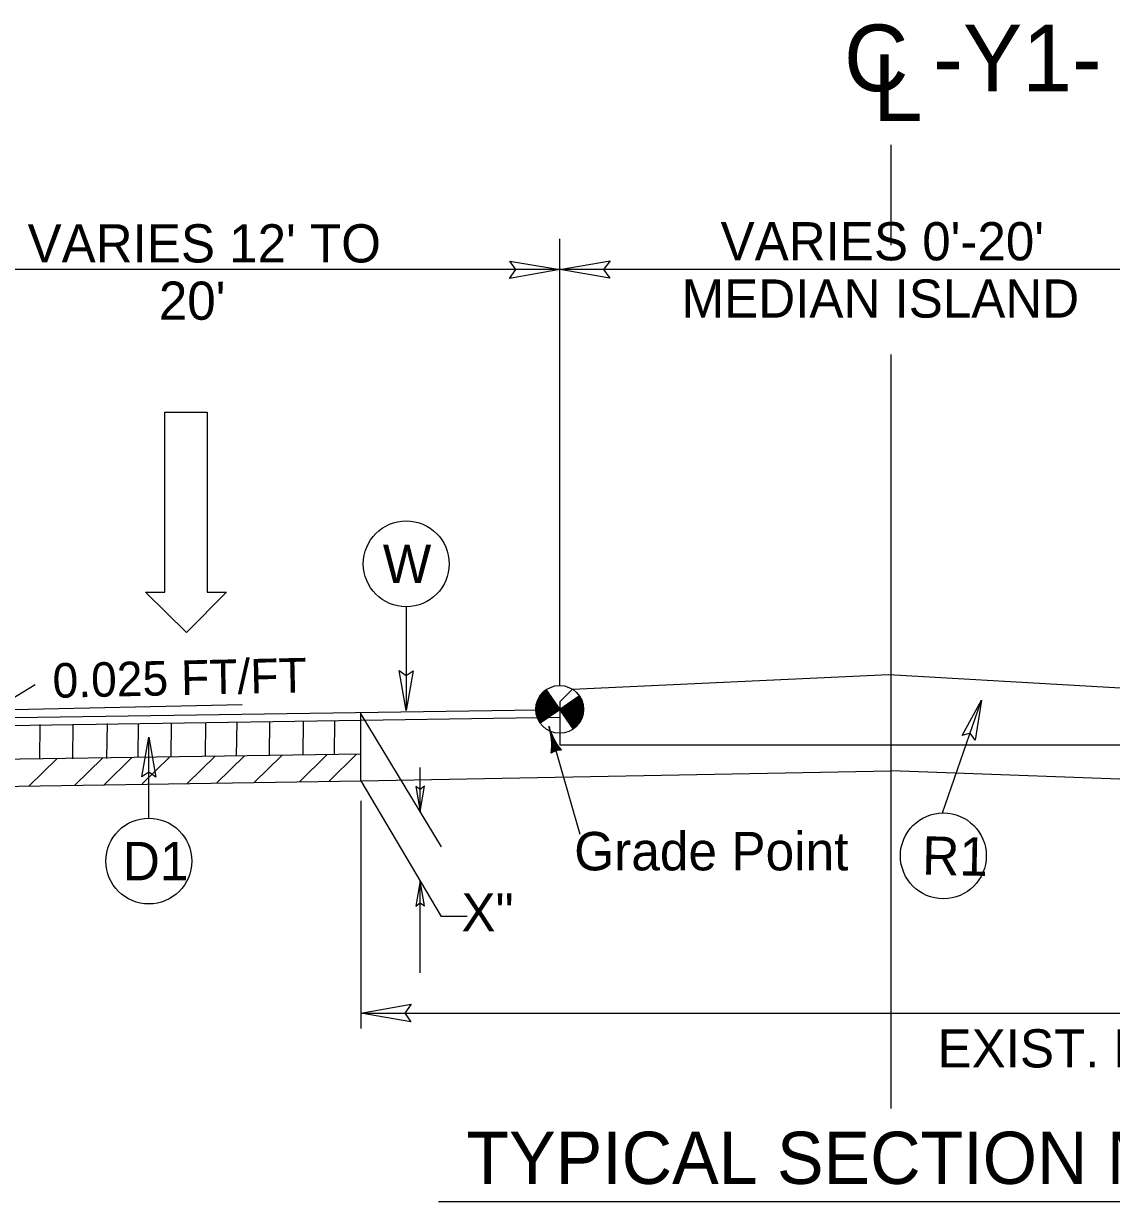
# Model space of a CAD drawing. Extents: x 2176156 to 2177167, y 76401 to 76644.
# Drawn here: x 2176967.78 to 2177000.61, y 76541.23 to 76576.8 of the extents above; entities that cross this region are included whole.
import ezdxf

# ---------------------------------------------------------------- set-up
doc = ezdxf.new("R2010")
doc.units = 0
for name, color, linetype in [('Exist Building', 7, 'Continuous'), ('Exist Building Metal Canopy', 7, 'Continuous'), ('Exist Roads Change in Surface', 7, 'Continuous'), ('Exist Roads Curbs', 7, 'Continuous'), ('Exist Roads Soil', 7, 'Continuous'), ('Exist Structure Minor Culvert Topo', 7, 'Continuous'), ('Exist Structure Minor Drop Inlet', 7, 'Continuous'), ('Exist Utilities Other Pole CELL', 7, 'Continuous'), ('Exist Vegetation Woods Line', 7, 'Continuous'), ('Model Boundary Lines Text', 7, 'Continuous'), ('Old_Level_1', 7, 'Continuous'), ('Old_Level_3', 7, 'Continuous'), ('Prop North Arrow NAD83 for Plan Sheets CELL', 7, 'Continuous'), ('Sheet Plan CELL', 7, 'Continuous')]:
    doc.layers.add(name, color=color, linetype=linetype)

msp = doc.modelspace()

# ---------------------------------------------------------------- linework, layer by layer
at = {"layer": 'Exist Building'}
for p, q in [((2176977.96, 76553.929), (2176977.96, 76556.001)), ((2176942.857, 76553.407), (2176977.96, 76553.929))]:
    msp.add_line(p, q, dxfattribs=at)
at = {"layer": 'Exist Roads Change in Surface'}
for p, q in [((2176983.548, 76556.682), (2176983.96, 76556.091)), ((2176983.96, 76556.091), (2176984.551, 76556.502)), ((2176983.367, 76555.68), (2176983.96, 76556.091)), ((2176983.96, 76556.091), (2176983.367, 76555.68)), ((2176984.371, 76555.499), (2176983.96, 76556.091))]:
    msp.add_line(p, q, dxfattribs=at)
for points in [[(2176983.714, 76556.443), (2176983.239, 76556.112)], [(2176983.698, 76556.467), (2176983.24, 76556.148)], [(2176983.706, 76556.455), (2176983.24, 76556.13)], [(2176983.69, 76556.478), (2176983.243, 76556.167)], [(2176983.682, 76556.49), (2176983.245, 76556.187)], [(2176983.673, 76556.502), (2176983.247, 76556.206)], [(2176983.665, 76556.514), (2176983.251, 76556.226)], [(2176983.657, 76556.526), (2176983.256, 76556.247)], [(2176983.649, 76556.538), (2176983.261, 76556.268)], [(2176983.64, 76556.549), (2176983.267, 76556.29)], [(2176983.632, 76556.561), (2176983.273, 76556.311)], [(2176983.624, 76556.573), (2176983.281, 76556.334)], [(2176983.616, 76556.585), (2176983.29, 76556.358)], [(2176983.607, 76556.597), (2176983.3, 76556.383)], [(2176983.599, 76556.609), (2176983.313, 76556.409)], [(2176983.591, 76556.62), (2176983.327, 76556.437)], [(2176983.583, 76556.632), (2176983.343, 76556.466)], [(2176983.574, 76556.644), (2176983.363, 76556.497)], [(2176983.566, 76556.656), (2176983.39, 76556.533)], [(2176983.558, 76556.668), (2176983.424, 76556.574)], [(2176983.55, 76556.68), (2176983.485, 76556.635)], [(2176984.555, 76556.497), (2176984.555, 76556.497), (2176983.963, 76556.085)], [(2176984.563, 76556.485), (2176983.972, 76556.073)], [(2176984.57, 76556.472), (2176983.98, 76556.062)], [(2176984.578, 76556.461), (2176983.988, 76556.05)], [(2176984.585, 76556.448), (2176983.996, 76556.038)], [(2176983.723, 76556.431), (2176983.239, 76556.094)], [(2176983.731, 76556.419), (2176983.239, 76556.077)], [(2176983.739, 76556.407), (2176983.24, 76556.06)], [(2176983.747, 76556.396), (2176983.24, 76556.042)], [(2176983.756, 76556.384), (2176983.242, 76556.026)], [(2176983.764, 76556.372), (2176983.243, 76556.01)], [(2176983.772, 76556.36), (2176983.245, 76555.993)], [(2176983.78, 76556.348), (2176983.248, 76555.978)], [(2176983.789, 76556.336), (2176983.251, 76555.962)], [(2176983.797, 76556.325), (2176983.254, 76555.947)], [(2176983.805, 76556.313), (2176983.257, 76555.931)], [(2176983.813, 76556.301), (2176983.26, 76555.916)], [(2176983.821, 76556.289), (2176983.264, 76555.901)], [(2176983.83, 76556.277), (2176983.268, 76555.887)], [(2176983.838, 76556.265), (2176983.273, 76555.872)], [(2176983.846, 76556.254), (2176983.278, 76555.858)], [(2176983.854, 76556.242), (2176983.283, 76555.844)], [(2176983.863, 76556.23), (2176983.288, 76555.83)], [(2176983.871, 76556.218), (2176983.294, 76555.816)], [(2176983.879, 76556.206), (2176983.299, 76555.803)], [(2176983.887, 76556.194), (2176983.305, 76555.789)], [(2176983.896, 76556.183), (2176983.312, 76555.776)], [(2176983.904, 76556.171), (2176983.317, 76555.763)], [(2176983.912, 76556.159), (2176983.324, 76555.75)], [(2176983.92, 76556.147), (2176983.331, 76555.737)], [(2176983.929, 76556.135), (2176983.338, 76555.724)], [(2176983.937, 76556.123), (2176983.346, 76555.713)], [(2176983.945, 76556.112), (2176983.353, 76555.7)], [(2176983.953, 76556.1), (2176983.362, 76555.688), (2176983.362, 76555.688)], [(2176984.592, 76556.435), (2176984.004, 76556.026)], [(2176984.599, 76556.422), (2176984.013, 76556.014)], [(2176984.606, 76556.41), (2176984.021, 76556.002)], [(2176984.613, 76556.397), (2176984.029, 76555.991)], [(2176984.619, 76556.383), (2176984.037, 76555.979)], [(2176984.624, 76556.37), (2176984.046, 76555.967)], [(2176984.63, 76556.356), (2176984.054, 76555.955)], [(2176984.635, 76556.342), (2176984.062, 76555.943)], [(2176984.64, 76556.328), (2176984.07, 76555.932)], [(2176984.645, 76556.314), (2176984.079, 76555.92)], [(2176984.65, 76556.299), (2176984.087, 76555.908)], [(2176984.654, 76556.285), (2176984.095, 76555.896)], [(2176984.658, 76556.27), (2176984.103, 76555.884)], [(2176984.661, 76556.255), (2176984.112, 76555.872)], [(2176984.664, 76556.239), (2176984.12, 76555.86)], [(2176984.667, 76556.224), (2176984.128, 76555.849)], [(2176984.67, 76556.208), (2176984.136, 76555.837)], [(2176984.673, 76556.193), (2176984.145, 76555.825)], [(2176984.675, 76556.176), (2176984.153, 76555.813)], [(2176984.676, 76556.16), (2176984.161, 76555.801)], [(2176984.678, 76556.144), (2176984.169, 76555.789)], [(2176984.68, 76556.127), (2176984.177, 76555.778)], [(2176984.68, 76556.11), (2176984.186, 76555.766)], [(2176984.68, 76556.093), (2176984.194, 76555.754)], [(2176984.679, 76556.074), (2176984.202, 76555.742)], [(2176984.68, 76556.057), (2176984.21, 76555.73)], [(2176984.679, 76556.039), (2176984.219, 76555.718)], [(2176984.677, 76556.02), (2176984.227, 76555.707)], [(2176984.674, 76556), (2176984.235, 76555.695)], [(2176984.672, 76555.981), (2176984.243, 76555.683)], [(2176984.668, 76555.961), (2176984.252, 76555.671)], [(2176984.665, 76555.941), (2176984.26, 76555.659)], [(2176984.66, 76555.92), (2176984.268, 76555.647)], [(2176984.654, 76555.898), (2176984.276, 76555.636)], [(2176984.647, 76555.876), (2176984.285, 76555.624)], [(2176984.64, 76555.854), (2176984.293, 76555.612)], [(2176984.631, 76555.83), (2176984.301, 76555.6)], [(2176984.621, 76555.805), (2176984.309, 76555.588)], [(2176984.609, 76555.78), (2176984.317, 76555.577)], [(2176984.597, 76555.753), (2176984.326, 76555.565)], [(2176984.58, 76555.724), (2176984.334, 76555.553)], [(2176984.56, 76555.693), (2176984.342, 76555.541)], [(2176984.536, 76555.658), (2176984.35, 76555.529)], [(2176984.503, 76555.618), (2176984.359, 76555.517)], [(2176984.451, 76555.564), (2176984.367, 76555.505)]]:
    msp.add_lwpolyline(points, dxfattribs=at)
msp.add_circle((2176983.959, 76556.091), 0.721, dxfattribs=at)
for start, end in [(124.8249, 214.8249), (304.8249, 34.8249)]:
    msp.add_arc((2176983.959, 76556.091), 0.721, start, end, dxfattribs=at)
at = {"layer": 'Exist Roads Curbs'}
msp.add_lwpolyline([(2176959.96, 76555.734), (2176983.96, 76556.091), (2176983.96, 76556.091), (2176983.96, 76555.841), (2176983.96, 76555.841), (2176959.96, 76555.484)], close=True, dxfattribs=at)
at = {"layer": 'Exist Roads Soil'}
for p, q in [((2176984.343, 76556.698), (2176993.894, 76557.141)), ((2176993.894, 76557.141), (2177003.554, 76556.588)), ((2176983.96, 76556.323), (2176984.343, 76556.698)), ((2176983.96, 76556.323), (2176983.96, 76555.024)), ((2176983.96, 76555.024), (2177003.96, 76555.024)), ((2176977.96, 76554.735), (2176959.467, 76554.46))]:
    msp.add_line(p, q, dxfattribs=at)
at = {"layer": 'Exist Structure Minor Drop Inlet'}
for p, q in [((2176972.04, 76559.632), (2176972.04, 76565.064)), ((2176972.04, 76565.064), (2176973.32, 76565.064)), ((2176973.32, 76565.064), (2176973.32, 76559.632)), ((2176972.7, 76558.41), (2176971.458, 76559.632)), ((2176971.458, 76559.632), (2176972.04, 76559.632)), ((2176973.902, 76559.632), (2176972.7, 76558.41)), ((2176973.32, 76559.632), (2176973.902, 76559.632))]:
    msp.add_line(p, q, dxfattribs=at)
at = {"layer": 'Exist Utilities Other Pole CELL'}
for q in [(2176968.128, 76556.841), (2176974.374, 76556.24)]:
    msp.add_line((2176966.868, 76556.076), q, dxfattribs=at)
at = {"layer": 'Model Boundary Lines Text'}
for p, q in [((2176976.218, 76554.718), (2176976.232, 76555.732)), ((2176977.158, 76554.725), (2176977.173, 76555.751)), ((2176968.265, 76554.59), (2176968.28, 76555.638)), ((2176969.262, 76554.593), (2176969.278, 76555.648)), ((2176970.294, 76554.605), (2176970.31, 76555.666)), ((2176971.235, 76554.635), (2176971.25, 76555.66)), ((2176972.232, 76554.651), (2176972.247, 76555.68)), ((2176973.265, 76554.679), (2176973.279, 76555.687)), ((2176974.205, 76554.679), (2176974.22, 76555.71)), ((2176975.2, 76554.704), (2176975.214, 76555.72)), ((2176972.72, 76553.854), (2176973.557, 76554.674)), ((2176973.604, 76553.863), (2176974.443, 76554.685)), ((2176974.737, 76553.88), (2176975.573, 76554.7)), ((2176976.102, 76553.9), (2176976.936, 76554.718)), ((2176976.991, 76553.914), (2176977.83, 76554.737)), ((2176967.946, 76553.779), (2176968.78, 76554.596)), ((2176969.321, 76553.797), (2176970.161, 76554.621)), ((2176970.213, 76553.815), (2176971.048, 76554.633)), ((2176971.355, 76553.841), (2176972.179, 76554.649)), ((2176980.299, 76541.231), (2177007.62, 76541.231))]:
    msp.add_line(p, q, dxfattribs=at)
at = {"layer": 'Old_Level_1'}
for points in [[(2176982.45, 76569.63), (2176983.96, 76569.37), (2176982.442, 76569.101), (2176982.635, 76569.37)], [(2176985.469, 76569.11), (2176983.96, 76569.37), (2176985.478, 76569.638), (2176985.285, 76569.37)], [(2176979.615, 76553.766), (2176979.747, 76553.011), (2176979.879, 76553.771), (2176979.746, 76553.674)], [(2176979.88, 76550.155), (2176979.748, 76550.909), (2176979.616, 76550.15), (2176979.75, 76550.247)], [(2176979.469, 76546.657), (2176977.96, 76546.917), (2176979.478, 76547.186), (2176979.285, 76546.917)]]:
    msp.add_lwpolyline(points, close=True, dxfattribs=at)
at = {"layer": 'Old_Level_3'}
for p, q in [((2176993.96, 76570.108), (2176993.96, 76573.137)), ((2176983.96, 76556.818), (2176983.96, 76570.297)), ((2176983.96, 76569.37), (2176963.96, 76569.37)), ((2177003.96, 76569.37), (2176983.96, 76569.37)), ((2176993.96, 76544.039), (2176993.96, 76566.807)), ((2176977.959, 76555.944), (2176980.384, 76551.936)), ((2176979.747, 76553.011), (2176979.747, 76554.339)), ((2176977.96, 76553.929), (2176980.385, 76549.834)), ((2176977.96, 76553.329), (2176977.96, 76546.449)), ((2176979.748, 76548.134), (2176979.748, 76550.909)), ((2176981.165, 76549.834), (2176980.385, 76549.834)), ((2176977.96, 76546.917), (2177019.952, 76546.917))]:
    msp.add_line(p, q, dxfattribs=at)
at = {"layer": 'Prop North Arrow NAD83 for Plan Sheets CELL'}
for p, q in [((2176979.328, 76559.189), (2176979.328, 76556.056)), ((2176995.512, 76552.962), (2176996.694, 76556.368)), ((2176984.581, 76552.315), (2176983.637, 76555.573)), ((2176971.558, 76552.806), (2176971.558, 76555.25))]:
    msp.add_line(p, q, dxfattribs=at)
for points in [[(2176979.535, 76557.256), (2176979.328, 76556.056), (2176979.115, 76557.262), (2176979.328, 76557.109)], [(2176996.106, 76555.302), (2176996.694, 76556.368), (2176996.501, 76555.158), (2176996.349, 76555.373)], [(2176971.352, 76554.05), (2176971.558, 76555.25), (2176971.772, 76554.044), (2176971.558, 76554.197)]]:
    msp.add_lwpolyline(points, close=True, dxfattribs=at)
for centre in [(2176979.328, 76560.485), (2176995.539, 76551.666), (2176971.558, 76551.51)]:
    msp.add_circle(centre, 1.296, dxfattribs=at)
for centre, radius, start, end in [((2176985.483, 76556.082), 1.915, 195.408, 219.6854), ((2176981.804, 76555.015), 1.915, 352.6547, 16.9321), ((2176985.483, 76556.082), 1.942, 205.7065, 218.9809), ((2176981.804, 76555.015), 1.942, 353.3593, 6.6337), ((2176981.804, 76555.015), 1.969, 353.9396, 2.7814), ((2176985.483, 76556.082), 1.969, 209.5588, 218.4006), ((2176983.973, 76554.412), 0.448, 85.4042, 126.9359), ((2176981.804, 76555.015), 1.995, 354.4201, 359.873), ((2176985.483, 76556.082), 1.995, 212.4671, 217.9201), ((2176981.804, 76555.015), 2.022, 354.8171, 357.4612), ((2176985.483, 76556.082), 2.022, 214.8789, 217.523)]:
    msp.add_arc(centre, radius, start, end, dxfattribs=at)
at = {"layer": 'Sheet Plan CELL'}
for p in [(2176977.96, 76553.929), (2177019.949, 76553.295)]:
    msp.add_line(p, (2176993.96, 76554.236), dxfattribs=at)

# ---------------------------------------------------------------- texts
at = {"layer": 'Exist Building Metal Canopy'}
msp.add_text('TYPICAL SECTION NO.  4', height=1.5766, rotation=0, dxfattribs=at).set_placement((2176981.144, 76541.76))
at = {"layer": 'Exist Structure Minor Culvert Topo'}
for s, height, p in [("VARIES 12' TO ", 1.15334, (2176967.899, 76569.586)), ("VARIES 0'-20' ", 1.15334, (2176988.816, 76569.65)), ("20'", 1.1533, (2176971.862, 76567.856)), ('MEDIAN ISLAND', 1.15334, (2176987.64, 76567.92)), ("EXIST. PAVEMENT 50'", 1.15334, (2176995.365, 76545.277))]:
    msp.add_text(s, height=height, dxfattribs=at).set_placement(p)
at = {"layer": 'Exist Utilities Other Pole CELL'}
msp.add_text('0.025 FT/FT', height=1.04295, rotation=1.2518, dxfattribs=at).set_placement((2176968.664, 76556.438))
at = {"layer": 'Exist Vegetation Woods Line'}
msp.add_text('C -Y1- & -Y4-', height=2.01314, dxfattribs=at).set_placement((2176992.539, 76574.757))
msp.add_text('L', height=2.013, rotation=359.9469, dxfattribs=at).set_placement((2176993.417, 76573.856))
at = {"layer": 'Prop North Arrow NAD83 for Plan Sheets CELL'}
for s, rotation, p in [('W', 0.0003, (2176978.621, 76559.905)), ('Grade Point', 0.0002, (2176984.397, 76551.229)), ('R1', 358.8249, (2176994.891, 76551.1)), ('D1', 0.0003, (2176970.773, 76550.93))]:
    msp.add_text(s, height=1.16, rotation=rotation, dxfattribs=at).set_placement(p)
msp.add_text('X"', height=1.1533, dxfattribs=at).set_placement((2176980.995, 76549.385))

doc.saveas('drawing.dxf')
